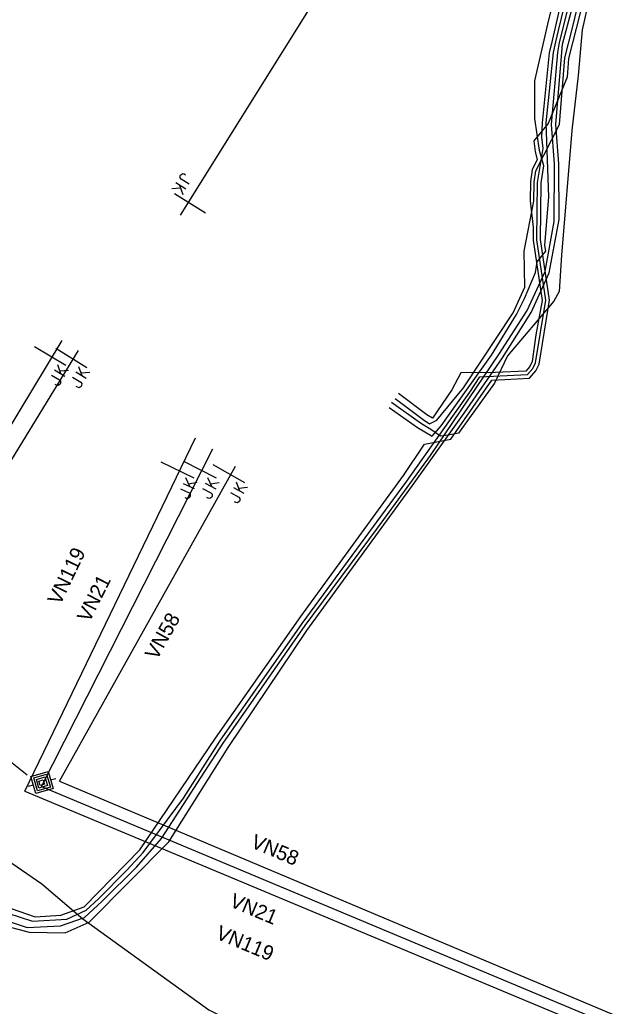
# Model space of a CAD drawing. Extents: x -540340 to -537226, y -1183949 to -1180375.
# Drawn here: x -537514.3 to -537473.4, y -1180690 to -1180622.4 of the extents above; entities that cross this region are included whole.
import ezdxf

# ---------------------------------------------------------------- set-up
doc = ezdxf.new("R2010")
doc.units = 0
for name, color, linetype in [('Vrstva 1', 7, 'Continuous'), ('Vrstva 13', 7, 'Continuous'), ('Vrstva 15', 7, 'Continuous'), ('Vrstva 18', 7, 'Continuous'), ('Vrstva 3', 7, 'Continuous'), ('Vrstva 5', 7, 'Continuous')]:
    doc.layers.add(name, color=color, linetype=linetype)

msp = doc.modelspace()

# ---------------------------------------------------------------- linework, layer by layer
at = {"layer": 'Vrstva 1'}
for points in [[(-537431.228, -1180479.977), (-537455.152, -1180540.114), (-537475.319, -1180590.928), (-537503.346, -1180635.787)], [(-537524.622, -1180666.267), (-537524.208, -1180665.581), (-537511.413, -1180644.384)], [(-537523.685, -1180666.914), (-537523.331, -1180666.336), (-537510.283, -1180645.074)], [(-537513.969, -1180675.242), (-537502.288, -1180651.049)], [(-537512.818, -1180674.917), (-537501.096, -1180651.802)], [(-537511.587, -1180674.55), (-537499.558, -1180652.994)], [(-537512.818, -1180674.917), (-537464.398, -1180695.213), (-537378.154, -1180692.497), (-537311.066, -1180689.983), (-537229.161, -1180685.674)], [(-537511.587, -1180674.55), (-537464.268, -1180694.509), (-537378.157, -1180691.538), (-537311.238, -1180689.012), (-537229.494, -1180684.766)], [(-537513.969, -1180675.242), (-537464.528, -1180695.917), (-537378.21, -1180693.509), (-537311.069, -1180690.923), (-537228.835, -1180686.565)]]:
    msp.add_lwpolyline(points, dxfattribs=at)
at = {"layer": 'Vrstva 13'}
for points in [[(-537513.56, -1180674.233), (-537512.381, -1180673.886)], [(-537513.212, -1180675.412), (-537513.56, -1180674.233)], [(-537513.359, -1180674.335), (-537512.476, -1180674.074)], [(-537513.099, -1180675.218), (-537513.359, -1180674.335)], [(-537513.178, -1180674.441), (-537512.589, -1180674.268)], [(-537513.005, -1180675.03), (-537513.178, -1180674.441)], [(-537513.006, -1180674.551), (-537512.711, -1180674.464)], [(-537512.711, -1180674.464), (-537512.624, -1180674.758)], [(-537512.589, -1180674.268), (-537512.415, -1180674.857)], [(-537512.476, -1180674.074), (-537512.215, -1180674.958)], [(-537512.381, -1180673.886), (-537512.034, -1180675.065)], [(-537512.207, -1180674.475), (-537511.849, -1180674.37)], [(-537513.386, -1180674.823), (-537513.745, -1180674.928)], [(-537512.034, -1180675.065), (-537513.212, -1180675.412)], [(-537512.215, -1180674.958), (-537513.099, -1180675.218)], [(-537512.919, -1180674.845), (-537513.006, -1180674.551)], [(-537512.415, -1180674.857), (-537513.005, -1180675.03)], [(-537512.624, -1180674.758), (-537512.919, -1180674.845)]]:
    msp.add_lwpolyline(points, dxfattribs=at)
at = {"layer": 'Vrstva 15'}
msp.add_lwpolyline([(-537513.8, -1180674.147), (-537515.762, -1180672.597)], dxfattribs=at)
at = {"layer": 'Vrstva 18'}
for points in [[(-537503.344, -1180633.233), (-537503.33, -1180633.08)], [(-537503.273, -1180633.324), (-537503.344, -1180633.233)], [(-537503.33, -1180633.08), (-537503.298, -1180633.029)], [(-537503.298, -1180633.029), (-537503.162, -1180632.941)], [(-537503.162, -1180632.941), (-537503.054, -1180632.973)], [(-537503.054, -1180632.973), (-537502.971, -1180633.025)], [(-537502.941, -1180634.019), (-537503.643, -1180633.58)], [(-537503.376, -1180633.747), (-537503.16, -1180634.369)], [(-537502.722, -1180633.668), (-537503.273, -1180633.324)], [(-537503.306, -1180633.953), (-537503.898, -1180633.989)], [(-537501.593, -1180635.65), (-537503.713, -1180634.325)], [(-537513.304, -1180644.779), (-537511.163, -1180646.071)], [(-537511.843, -1180644.913), (-537509.712, -1180646.22)], [(-537511.492, -1180646.654), (-537511.717, -1180646.036)], [(-537512.144, -1180646.743), (-537511.588, -1180647.079)], [(-537511.93, -1180646.389), (-537511.222, -1180646.817)], [(-537511.564, -1180646.45), (-537510.973, -1180646.404)], [(-537510.482, -1180646.533), (-537509.777, -1180646.966)], [(-537510.045, -1180646.801), (-537510.266, -1180646.181)], [(-537510.116, -1180646.596), (-537509.525, -1180646.555)], [(-537511.801, -1180647.433), (-537511.886, -1180647.382)], [(-537511.694, -1180647.464), (-537511.801, -1180647.433)], [(-537511.558, -1180647.373), (-537511.694, -1180647.464)], [(-537511.588, -1180647.079), (-537511.516, -1180647.169)], [(-537511.528, -1180647.322), (-537511.558, -1180647.373)], [(-537511.516, -1180647.169), (-537511.528, -1180647.322)], [(-537510.698, -1180646.886), (-537510.144, -1180647.225)], [(-537510.144, -1180647.225), (-537510.073, -1180647.316)], [(-537510.073, -1180647.316), (-537510.086, -1180647.469)], [(-537510.361, -1180647.578), (-537510.444, -1180647.526)], [(-537510.253, -1180647.609), (-537510.361, -1180647.578)], [(-537510.117, -1180647.519), (-537510.253, -1180647.609)], [(-537510.086, -1180647.469), (-537510.117, -1180647.519)], [(-537504.651, -1180652.691), (-537502.397, -1180653.773)], [(-537503.11, -1180652.647), (-537500.88, -1180653.778)], [(-537501.107, -1180652.868), (-537498.929, -1180654.096)], [(-537503.131, -1180654.163), (-537502.385, -1180654.521)], [(-537502.669, -1180654.385), (-537502.952, -1180653.791)], [(-537502.76, -1180654.188), (-537502.176, -1180654.086)], [(-537501.622, -1180654.152), (-537500.885, -1180654.526)], [(-537501.165, -1180654.384), (-537501.435, -1180653.784)], [(-537501.253, -1180654.185), (-537500.666, -1180654.096)], [(-537499.241, -1180654.688), (-537499.484, -1180654.077)], [(-537503.309, -1180654.536), (-537502.724, -1180654.817)], [(-537502.724, -1180654.817), (-537502.643, -1180654.899)], [(-537501.809, -1180654.521), (-537501.23, -1180654.815)], [(-537501.23, -1180654.815), (-537501.151, -1180654.899)], [(-537499.89, -1180654.797), (-537499.324, -1180655.116)], [(-537499.687, -1180654.437), (-537498.966, -1180654.843)], [(-537499.319, -1180654.486), (-537498.73, -1180654.423)], [(-537502.902, -1180655.19), (-537502.991, -1180655.147)], [(-537502.792, -1180655.21), (-537502.902, -1180655.19)], [(-537502.666, -1180655.107), (-537502.792, -1180655.21)], [(-537502.64, -1180655.053), (-537502.666, -1180655.107)], [(-537502.643, -1180654.899), (-537502.64, -1180655.053)], [(-537501.417, -1180655.183), (-537501.504, -1180655.139)], [(-537501.307, -1180655.206), (-537501.417, -1180655.183)], [(-537501.178, -1180655.106), (-537501.307, -1180655.206)], [(-537501.152, -1180655.053), (-537501.178, -1180655.106)], [(-537501.151, -1180654.899), (-537501.152, -1180655.053)], [(-537499.527, -1180655.476), (-537499.613, -1180655.428)], [(-537499.418, -1180655.504), (-537499.527, -1180655.476)], [(-537499.286, -1180655.409), (-537499.418, -1180655.504)], [(-537499.324, -1180655.116), (-537499.249, -1180655.204)], [(-537499.256, -1180655.357), (-537499.286, -1180655.409)], [(-537499.249, -1180655.204), (-537499.256, -1180655.357)]]:
    msp.add_lwpolyline(points, dxfattribs=at)
at = {"layer": 'Vrstva 5'}
for points in [[(-537467.817, -1180515.673), (-537459.353, -1180567.48), (-537459.028, -1180571.968), (-537461.547, -1180579.448), (-537463.756, -1180585.36), (-537464.58, -1180587.35), (-537466.716, -1180594.682), (-537470.608, -1180606.576), (-537474.396, -1180616.804), (-537475.822, -1180623.101), (-537476.089, -1180626.222), (-537476.516, -1180629.989), (-537477.242, -1180638.543), (-537477.395, -1180641.021), (-537477.755, -1180641.693), (-537480.923, -1180645.42), (-537481.828, -1180647.304), (-537483.827, -1180650.087), (-537484.284, -1180650.723), (-537485.002, -1180650.872), (-537485.527, -1180650.934), (-537486.103, -1180650.524), (-537486.877, -1180650.046), (-537488.87, -1180648.62)], [(-537514.902, -1180683.27), (-537513.267, -1180683.855), (-537511.507, -1180683.736), (-537509.899, -1180683.17), (-537506.102, -1180679.26), (-537500.909, -1180671.617), (-537495.086, -1180663.274), (-537488.04, -1180653.622), (-537486.603, -1180651.472), (-537484.819, -1180651.126), (-537482, -1180647.087), (-537481.109, -1180647.045), (-537479.415, -1180646.959), (-537478.984, -1180646.448), (-537478.767, -1180646), (-537478.052, -1180641.612), (-537478.682, -1180637.464), (-537478.616, -1180633.572), (-537478.435, -1180632.41), (-537478.75, -1180631.374), (-537479.059, -1180629.179), (-537479.058, -1180626.599), (-537478.166, -1180622.722), (-537476.246, -1180614.995)], [(-537515.124, -1180683.606), (-537513.442, -1180684.149), (-537511.083, -1180684), (-537509.765, -1180683.382), (-537508.931, -1180682.627), (-537506.996, -1180680.653), (-537505.876, -1180679.443), (-537503.117, -1180675.713), (-537500.627, -1180671.828), (-537494.991, -1180663.756), (-537487.81, -1180654.006), (-537483.519, -1180647.906), (-537482.834, -1180646.869), (-537479.552, -1180646.716), (-537479.201, -1180646.291), (-537479.005, -1180645.906), (-537478.303, -1180641.619), (-537478.932, -1180637.481), (-537478.866, -1180633.549), (-537478.489, -1180631.229), (-537478.589, -1180630.458), (-537478.542, -1180629.473), (-537478.046, -1180624.672), (-537477.857, -1180623.841), (-537477.647, -1180622.947), (-537476.264, -1180616.797)], [(-537488.609, -1180648.36), (-537486.697, -1180649.799), (-537486.259, -1180650.092), (-537485.764, -1180649.826), (-537483.931, -1180647.61), (-537480.54, -1180642.481), (-537479.736, -1180640.723), (-537479.799, -1180638.268), (-537479.127, -1180634.833), (-537479.116, -1180633.526), (-537478.997, -1180632.749), (-537477.366, -1180629.59), (-537477, -1180625.022), (-537476.493, -1180622.964), (-537474.96, -1180616.615)], [(-537474.636, -1180616.733), (-537476.752, -1180625.062), (-537476.856, -1180626.332), (-537478.138, -1180629.525), (-537479.126, -1180630.699), (-537479.038, -1180631.427), (-537478.89, -1180631.996), (-537479.238, -1180632.671), (-537479.366, -1180633.506), (-537479.377, -1180634.808), (-537479.17, -1180636.647), (-537479.182, -1180637.498), (-537478.554, -1180641.628), (-537478.983, -1180643.984), (-537479.245, -1180645.827), (-537479.411, -1180646.153), (-537479.672, -1180646.469), (-537481.75, -1180646.57), (-537484.12, -1180646.6), (-537484.747, -1180647.755), (-537486.066, -1180649.695), (-537486.449, -1180649.461), (-537488.397, -1180648.001)], [(-537515.324, -1180684.078), (-537513.804, -1180684.574), (-537511.535, -1180684.457), (-537509.879, -1180683.887), (-537508.666, -1180682.784), (-537506.322, -1180680.44), (-537504.604, -1180678.488), (-537500.392, -1180671.964), (-537494.788, -1180663.902), (-537489.833, -1180657.241), (-537486.19, -1180652.265), (-537481.519, -1180645.329), (-537479.581, -1180642.322), (-537478.36, -1180639.643), (-537477.74, -1180636.239), (-537477.724, -1180632.289), (-537477.918, -1180629.588), (-537477.476, -1180624.643), (-537477.379, -1180623.98), (-537476.132, -1180619.061)], [(-537489.025, -1180648.966), (-537487.095, -1180650.345), (-537486.096, -1180650.934), (-537485.462, -1180650.212), (-537483.731, -1180647.773), (-537482.035, -1180645.385), (-537480.321, -1180642.603), (-537479.763, -1180641.51), (-537479.012, -1180639.711), (-537478.902, -1180638.98), (-537478.309, -1180638.271), (-537478.371, -1180637.882), (-537478.091, -1180634.529), (-537478.291, -1180629.481), (-537477.789, -1180624.65), (-537477.625, -1180623.931), (-537477.44, -1180623.151), (-537476.44, -1180618.983)], [(-537515.228, -1180684.492), (-537513.669, -1180684.903), (-537511.206, -1180684.94), (-537509.553, -1180684.217), (-537504.104, -1180678.704), (-537500.041, -1180672.254), (-537494.666, -1180664.229), (-537487.428, -1180654.314), (-537483.888, -1180649.35), (-537481.282, -1180645.572), (-537479.317, -1180642.467), (-537478.072, -1180639.734), (-537477.389, -1180636.086), (-537477.424, -1180632.28), (-537477.617, -1180629.59), (-537477.167, -1180624.083), (-537475.839, -1180619.126)], [(-537530.88, -1180661.777), (-537532.373, -1180661.319), (-537533.384, -1180662.138), (-537534.594, -1180663.747), (-537534.304, -1180664.462), (-537528.918, -1180669.148), (-537521.77, -1180675.432), (-537512.808, -1180681.594), (-537509.997, -1180683.987), (-537501.368, -1180690.23), (-537495.897, -1180693.015), (-537484.881, -1180695.744), (-537477.363, -1180695.954), (-537470.096, -1180697.063), (-537463.413, -1180697.101), (-537453.89, -1180696.053), (-537446.059, -1180695.542), (-537435.563, -1180695.142), (-537412.336, -1180694.313)]]:
    msp.add_lwpolyline(points, dxfattribs=at)

# ---------------------------------------------------------------- texts
at = {"layer": 'Vrstva 3'}
for s, rotation, p in [('VN119', 64.228, (-537511.557, -1180662.559)), ('VN21', 63.11, (-537509.557, -1180663.747)), ('VN58', 60.837, (-537504.931, -1180666.319)), ('VN58', 337.13, (-537498.569, -1180679.071)), ('VN21', 337.258, (-537500.021, -1180683.118)), ('VN119', 337.307, (-537500.964, -1180685.318))]:
    msp.add_text(s, height=1, rotation=rotation, dxfattribs=at).set_placement(p)

doc.saveas('drawing.dxf')
